(* LS Electric XG5000 project: SSW900_EIP_Implicit *)
(* PLC LSPLC *)
(* module base 0 slot 0: Input/Output Module:XEM-DR14H2 (DC 24V Input 8 Contacts, Relay Output 6 Contacts) *)
(* module base 0 slot 1: Internal Positioning:XBF-PO02E (Open Collector Type, 2 Axis) *)
(* module base 0 slot 2: EtherNet/IP:XBL-EIPT (EtherNet/IP communication module, electrical) *)
VAR_GLOBAL
    SSW900_Ctrl : SSW900_Ctrl_typ; (* Control variable for SSW900 *)
    SSW900_In : WORD; (* Input data from SSW900 Implicit Connection *)
    SSW900_Out : WORD; (* Output data from SSW900 Implicit Connection *)
    SSW900_Status : SSW900_Status_typ; (* Status variable for SSW900 *)
END_VAR

TYPE SSW900_Status_typ : (* data type for SSW900 Status *)
STRUCT
    Running : BOOL; (* Status that SSW900 is running *)
    Gen_Enabled : BOOL; (* Status that SSW900 Gen is enabled *)
    Jogging : BOOL; (* Status that SSW900 is Jogging *)
    Initial_Test : BOOL; (* Status that SSW900 Initial Test is active *)
    Ramp_Up : BOOL; (* Status that SSW900 is ramping up *)
    Full_Voltage : BOOL; (* Status of SSW900 Full Voltage *)
    Bypass : BOOL; (* Status of SSW900 Bypass *)
    Ramp_Down : BOOL; (* Status of SSW900 is ramping down *)
    Remote : BOOL; (* Status that SSW900 is being remote controlled *)
    Braking : BOOL; (* Status that SSW900 is braking *)
    FWD_REV : BOOL; (* Status of SSW900 FWD or REV direction *)
    Reverse : BOOL; (* Status of SSW900 Reverse *)
    Ton : BOOL; (* Status of SSW900 Ton *)
    Toff : BOOL; (* Status of SSW900 Toff *)
    Alarm : BOOL; (* Status of SSW900 Alarm *)
    Fault : BOOL; (* Status of SSW900 Fault *)
END_STRUCT;
END_TYPE

TYPE SSW900_Ctrl_typ : (* data type for controlling SSW900 *)
STRUCT
    Start : BOOL; (* 0 = Stop;  1 = Start *)
    Gen_Enable : BOOL; (* Gen Enable for SSW900 *)
    Jog : BOOL; (* Jog command *)
    FWD_REV : BOOL; (* 0 = FWD direction;  1 = REV direction *)
    LOC_REM : BOOL; (* 0 =  Local Control;  1 = Remote Control *)
    Reset : BOOL; (* Reset Fault *)
END_STRUCT;
END_TYPE

PROGRAM SSW900_EIP (* task: Scan Program *)
(* Program to break out bits of SSW900 EIP Connection *)
VAR_EXTERNAL
    SSW900_Ctrl : SSW900_Ctrl_typ; (* Control variable for SSW900 *)
    SSW900_In : WORD; (* Input data from SSW900 Implicit Connection *)
    SSW900_Out : WORD; (* Output data from SSW900 Implicit Connection *)
    SSW900_Status : SSW900_Status_typ; (* Status variable for SSW900 *)
END_VAR

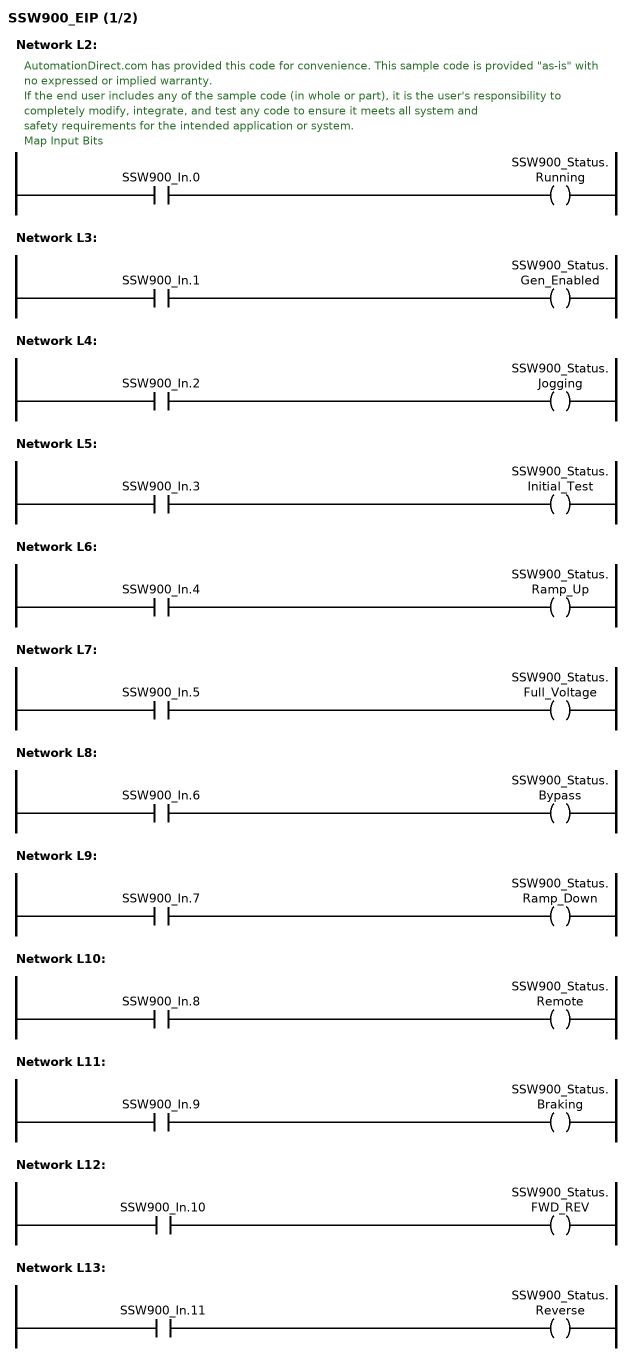
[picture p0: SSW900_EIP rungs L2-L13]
(* AutomationDirect.com has provided this code for convenience. This sample code is provided "as-is" with no expressed or implied warranty. / If the end user includes any of the sample code (in whole or part), it is the user's responsibility to completely modify, integrate, and test any code to ensure it meets all system and / safety requirements for the intended application or system. *)
(* Map Input Bits *)
(* Rung L2 *)
SSW900_Status.Running := SSW900_In.0;
(* Rung L3 *)
SSW900_Status.Gen_Enabled := SSW900_In.1;
(* Rung L4 *)
SSW900_Status.Jogging := SSW900_In.2;
(* Rung L5 *)
SSW900_Status.Initial_Test := SSW900_In.3;
(* Rung L6 *)
SSW900_Status.Ramp_Up := SSW900_In.4;
(* Rung L7 *)
SSW900_Status.Full_Voltage := SSW900_In.5;
(* Rung L8 *)
SSW900_Status.Bypass := SSW900_In.6;
(* Rung L9 *)
SSW900_Status.Ramp_Down := SSW900_In.7;
(* Rung L10 *)
SSW900_Status.Remote := SSW900_In.8;
(* Rung L11 *)
SSW900_Status.Braking := SSW900_In.9;
(* Rung L12 *)
SSW900_Status.FWD_REV := SSW900_In.10;
(* Rung L13 *)
SSW900_Status.Reverse := SSW900_In.11;

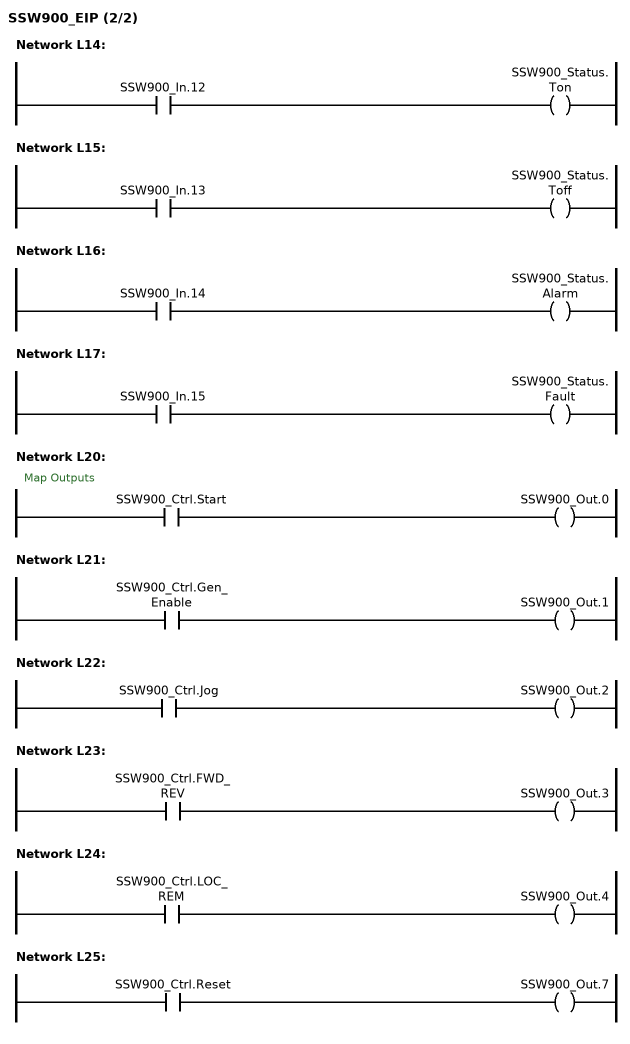
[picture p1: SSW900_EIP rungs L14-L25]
(* Rung L14 *)
SSW900_Status.Ton := SSW900_In.12;
(* Rung L15 *)
SSW900_Status.Toff := SSW900_In.13;
(* Rung L16 *)
SSW900_Status.Alarm := SSW900_In.14;
(* Rung L17 *)
SSW900_Status.Fault := SSW900_In.15;
(* Map Outputs *)
(* Rung L20 *)
SSW900_Out.0 := SSW900_Ctrl.Start;
(* Rung L21 *)
SSW900_Out.1 := SSW900_Ctrl.Gen_Enable;
(* Rung L22 *)
SSW900_Out.2 := SSW900_Ctrl.Jog;
(* Rung L23 *)
SSW900_Out.3 := SSW900_Ctrl.FWD_REV;
(* Rung L24 *)
SSW900_Out.4 := SSW900_Ctrl.LOC_REM;
(* Rung L25 *)
SSW900_Out.7 := SSW900_Ctrl.Reset;
END_PROGRAM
